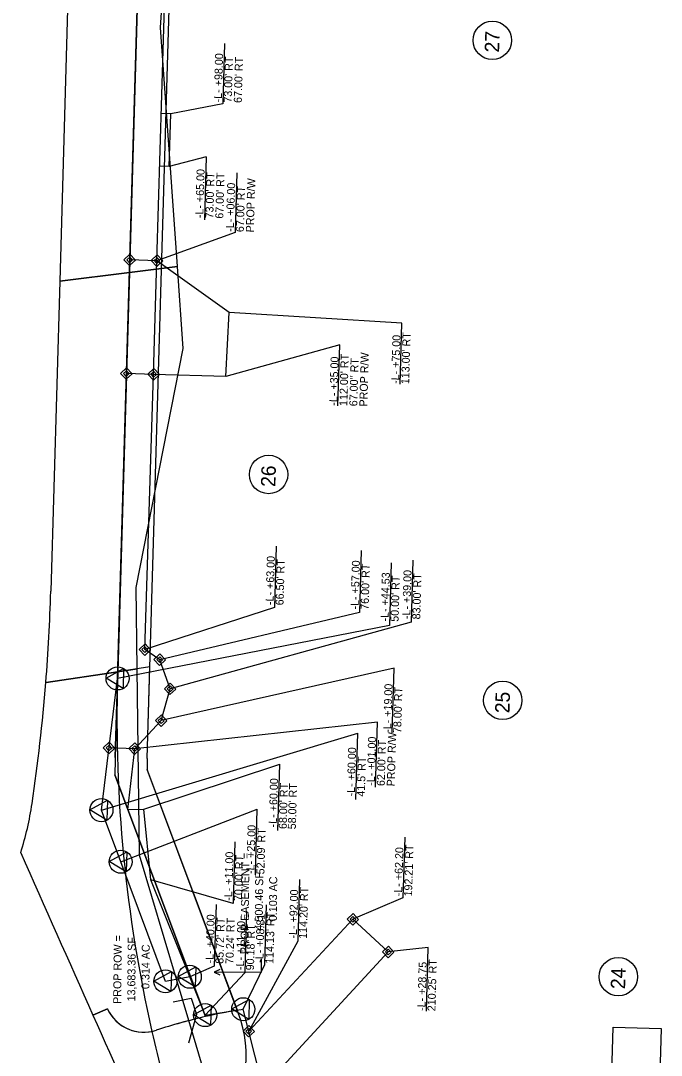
# Model space of a CAD drawing. Extents: x 2097272 to 2098144, y 685104 to 689282.
# Drawn here: x 2097691 to 2098091, y 685927 to 686573 of the extents above; entities that cross this region are included whole.
import ezdxf

# ---------------------------------------------------------------- set-up
doc = ezdxf.new("R2010")
doc.units = 0
for name, color, linetype in [('Prop Easement Construction', 7, 'Continuous'), ('Prop Easement Construction Station Offsets', 7, 'Continuous'), ('Prop Easement Permanent Drainage Utility', 7, 'Continuous'), ('Prop Easement Permanent Drainage Utility Station Offsets', 7, 'Continuous'), ('Prop Easement Permanent Utility', 7, 'Continuous'), ('Prop Easement Permanent Utility Station Offsets', 7, 'Continuous'), ('Prop Easement Temporary Drainage', 7, 'Continuous'), ('Prop Easement Temporary Drainage Station Offsets', 7, 'Continuous'), ('Prop Parcel Number CELL', 7, 'Continuous'), ('Prop ROW Marker CELL', 7, 'Continuous'), ('Prop ROW Permanent Easement CELL', 7, 'Continuous'), ('Prop ROW RW Lines', 7, 'Continuous'), ('Prop ROW Station Offsets', 7, 'Continuous'), ('Scratch_Level_3', 7, 'Continuous'), ('Scratch_Level_5', 7, 'Continuous'), ('Scratch_Level_6', 7, 'Continuous'), ('Scratch_Level_7', 7, 'Continuous')]:
    doc.layers.add(name, color=color, linetype=linetype)

msp = doc.modelspace()

# ---------------------------------------------------------------- linework, layer by layer
at = {"layer": 'Prop Easement Construction'}
for p, q in [((2097785.08, 686514.81), (2097779.09, 686514.98)), ((2097784.12, 686481.82), (2097785.08, 686514.81)), ((2097784.12, 686481.82), (2097778.13, 686482)), ((2097758.24, 686080.27), (2097762.55, 686118.29)), ((2097758.24, 686080.27), (2097768.23, 686080.47)), ((2097772.63, 686036.38), (2097768.23, 686080.47)), ((2097796.9, 685975.9), (2097772.63, 686036.38))]:
    msp.add_line(p, q, dxfattribs=at)
at = {"layer": 'Prop Easement Construction Station Offsets'}
for p, q in [((2097818.67, 686558.72), (2097817.57, 686520.89)), ((2097817.57, 686520.89), (2097785.08, 686514.81)), ((2097807.18, 686487.95), (2097784.12, 686481.82)), ((2097807.18, 686487.95), (2097806.04, 686448.6)), ((2097768.23, 686080.47), (2097853.06, 686108.63)), ((2097851.85, 686067.2), (2097853.06, 686108.63)), ((2097825.03, 686060.17), (2097823.91, 686021.63)), ((2097823.91, 686021.63), (2097772.63, 686036.38))]:
    msp.add_line(p, q, dxfattribs=at)
at = {"layer": 'Prop Easement Permanent Drainage Utility'}
for p, q in [((2097776.41, 686423.02), (2097759.42, 686423.51)), ((2097774.35, 686352.05), (2097776.41, 686423.02)), ((2097774.35, 686352.05), (2097757.36, 686352.54))]:
    msp.add_line(p, q, dxfattribs=at)
at = {"layer": 'Prop Easement Permanent Drainage Utility Station Offsets'}
for p, q in [((2097826.22, 686477.88), (2097825.14, 686440.63)), ((2097825.14, 686440.63), (2097776.41, 686423.02))]:
    msp.add_line(p, q, dxfattribs=at)
at = {"layer": 'Prop Easement Permanent Utility'}
for p, q in [((2097768.85, 686180.14), (2097774.35, 686352.05)), ((2097778.17, 686173.86), (2097768.85, 686180.14)), ((2097784.65, 686155.67), (2097778.17, 686173.86)), ((2097779.07, 686135.82), (2097784.65, 686155.67)), ((2097762.55, 686118.29), (2097779.07, 686135.82)), ((2097762.55, 686118.29), (2097746.5, 686118.76)), ((2097898.73, 686011.78), (2097833.74, 685941.88)), ((2097920.79, 685991.37), (2097898.73, 686011.78)), ((2097842.65, 685906.79), (2097920.79, 685991.37))]:
    msp.add_line(p, q, dxfattribs=at)
msp.add_lwpolyline([(2097776.41, 686423.02), (2097781.44, 686595.95)], dxfattribs=at)
at = {"layer": 'Prop Easement Permanent Utility Station Offsets'}
for p, q in [((2097850.86, 686244.85), (2097849.74, 686206.41)), ((2097903.93, 686242.07), (2097902.81, 686203.4)), ((2097936.21, 686236.07), (2097935.08, 686197.36)), ((2097849.74, 686206.41), (2097768.85, 686180.14)), ((2097902.81, 686203.4), (2097778.17, 686173.86)), ((2097935.08, 686197.36), (2097784.65, 686155.67)), ((2097924.46, 686168.68), (2097779.07, 686135.82)), ((2097923.28, 686128.13), (2097924.46, 686168.68)), ((2097914.02, 686134.92), (2097762.55, 686118.29)), ((2097912.84, 686094.37), (2097914.02, 686134.92)), ((2097931.1, 686063.03), (2097929.99, 686025.16)), ((2097865.41, 686036.58), (2097864.29, 685998.04)), ((2097929.99, 686025.16), (2097898.73, 686011.78)), ((2097864.29, 685998.04), (2097833.74, 685941.88)), ((2097945.75, 685994.23), (2097920.79, 685991.37)), ((2097944.6, 685954.48), (2097945.75, 685994.23))]:
    msp.add_line(p, q, dxfattribs=at)
at = {"layer": 'Prop Easement Temporary Drainage'}
for p, q in [((2097821.49, 686390.7), (2097776.41, 686423.02)), ((2097819.33, 686350.74), (2097821.49, 686390.7)), ((2097819.33, 686350.74), (2097774.35, 686352.05))]:
    msp.add_line(p, q, dxfattribs=at)
at = {"layer": 'Prop Easement Temporary Drainage Station Offsets'}
for p, q in [((2097929.31, 686384.08), (2097821.49, 686390.7)), ((2097928.2, 686345.99), (2097929.31, 686384.08)), ((2097890.54, 686370.56), (2097819.33, 686350.74)), ((2097889.43, 686332.4), (2097890.54, 686370.56))]:
    msp.add_line(p, q, dxfattribs=at)
at = {"layer": 'Prop Parcel Number CELL'}
msp.add_lwpolyline([(2098058.38, 685844.55), (2098061.29, 685944.51), (2098091.27, 685943.64), (2098088.37, 685843.68)], close=True, dxfattribs=at)
for centre in [(2097985.79, 686560.59), (2097846.11, 686289.52), (2097992.27, 686148.48), (2098064.45, 685975.93)]:
    msp.add_circle(centre, 12, dxfattribs=at)
at = {"layer": 'Prop ROW Marker CELL'}
for p, q in [((2097759.42, 686423.51), (2097759.42, 686423.51)), ((2097776.41, 686423.02), (2097776.41, 686423.02)), ((2097757.36, 686352.54), (2097757.36, 686352.54)), ((2097774.35, 686352.05), (2097774.35, 686352.05)), ((2097751.82, 686162.16), (2097751.82, 686162.16)), ((2097784.65, 686155.67), (2097784.65, 686155.67)), ((2097779.07, 686135.82), (2097779.07, 686135.82)), ((2097746.5, 686118.76), (2097746.5, 686118.76)), ((2097762.55, 686118.29), (2097762.55, 686118.29)), ((2097741.74, 686079.93), (2097741.74, 686079.93)), ((2097753.77, 686047.73), (2097753.77, 686047.73)), ((2097898.73, 686011.78), (2097898.73, 686011.78)), ((2097920.79, 685991.37), (2097920.79, 685991.37)), ((2097781.69, 685973.01), (2097781.69, 685973.01)), ((2097796.9, 685975.9), (2097796.9, 685975.9)), ((2097830.26, 685955.58), (2097830.26, 685955.58)), ((2097806.52, 685951.94), (2097806.52, 685951.94)), ((2097833.74, 685941.88), (2097833.74, 685941.88))]:
    msp.add_line(p, q, dxfattribs=at)
for points in [[(2097755.24, 686155.8), (2097744.62, 686162.36), (2097755.6, 686168.3)], [(2097745.16, 686073.58), (2097734.54, 686080.14), (2097745.52, 686086.08)], [(2097757.19, 686041.38), (2097746.57, 686047.94), (2097757.55, 686053.88)], [(2097785.1, 685966.66), (2097774.49, 685973.22), (2097785.47, 685979.15)], [(2097800.32, 685969.55), (2097789.71, 685976.11), (2097800.68, 685982.05)], [(2097833.68, 685949.22), (2097823.06, 685955.79), (2097834.04, 685961.72)], [(2097809.93, 685945.59), (2097799.32, 685952.15), (2097810.3, 685958.08)]]:
    msp.add_lwpolyline(points, close=True, dxfattribs=at)
for centre in [(2097751.82, 686162.16), (2097741.74, 686079.93), (2097753.77, 686047.73), (2097781.69, 685973.01), (2097796.9, 685975.9), (2097806.52, 685951.94), (2097830.26, 685955.58)]:
    msp.add_circle(centre, 7.2, dxfattribs=at)
at = {"layer": 'Prop ROW Permanent Easement CELL'}
for p, q in [((2097768.85, 686180.14), (2097768.85, 686180.14)), ((2097778.17, 686173.86), (2097778.17, 686173.86))]:
    msp.add_line(p, q, dxfattribs=at)
for points in [[(2097755.82, 686423.62), (2097759.52, 686427.11), (2097763.02, 686423.41), (2097759.32, 686419.92)], [(2097757.62, 686423.57), (2097759.47, 686425.31), (2097761.22, 686423.46), (2097759.37, 686421.72)], [(2097772.81, 686423.12), (2097776.52, 686426.62), (2097780.01, 686422.92), (2097776.31, 686419.42)], [(2097774.61, 686423.07), (2097776.46, 686424.82), (2097778.21, 686422.97), (2097776.36, 686421.22)], [(2097753.76, 686352.65), (2097757.46, 686356.14), (2097760.95, 686352.44), (2097757.25, 686348.95)], [(2097755.56, 686352.6), (2097757.41, 686354.34), (2097759.16, 686352.49), (2097757.3, 686350.75)], [(2097770.75, 686352.15), (2097774.45, 686355.65), (2097777.95, 686351.95), (2097774.25, 686348.45)], [(2097772.55, 686352.1), (2097774.4, 686353.85), (2097776.15, 686352), (2097774.3, 686350.25)], [(2097765.25, 686180.24), (2097768.96, 686183.74), (2097772.45, 686180.03), (2097768.75, 686176.54)], [(2097767.05, 686180.19), (2097768.9, 686181.94), (2097770.65, 686180.09), (2097768.8, 686178.34)], [(2097774.57, 686173.97), (2097778.28, 686177.46), (2097781.77, 686173.76), (2097778.07, 686170.27)], [(2097776.37, 686173.92), (2097778.23, 686175.66), (2097779.97, 686173.81), (2097778.12, 686172.07)], [(2097781.05, 686155.77), (2097784.75, 686159.27), (2097788.24, 686155.56), (2097784.54, 686152.07)], [(2097782.85, 686155.72), (2097784.7, 686157.47), (2097786.45, 686155.62), (2097784.59, 686153.87)], [(2097775.47, 686135.93), (2097779.17, 686139.42), (2097782.67, 686135.72), (2097778.96, 686132.22)], [(2097777.27, 686135.87), (2097779.12, 686137.62), (2097780.87, 686135.77), (2097779.02, 686134.02)], [(2097742.9, 686118.87), (2097746.61, 686122.36), (2097750.1, 686118.66), (2097746.4, 686115.16)], [(2097744.7, 686118.81), (2097746.55, 686120.56), (2097748.3, 686118.71), (2097746.45, 686116.96)], [(2097758.95, 686118.4), (2097762.66, 686121.89), (2097766.15, 686118.19), (2097762.45, 686114.7)], [(2097760.75, 686118.35), (2097762.6, 686120.09), (2097764.35, 686118.24), (2097762.5, 686116.5)], [(2097895.14, 686011.89), (2097898.84, 686015.38), (2097902.33, 686011.68), (2097898.63, 686008.18)], [(2097896.94, 686011.83), (2097898.79, 686013.58), (2097900.53, 686011.73), (2097898.68, 686009.98)], [(2097917.19, 685991.48), (2097920.89, 685994.97), (2097924.38, 685991.27), (2097920.68, 685987.77)], [(2097918.99, 685991.42), (2097920.84, 685993.17), (2097922.59, 685991.32), (2097920.74, 685989.57)], [(2097830.14, 685941.99), (2097833.84, 685945.48), (2097837.34, 685941.78), (2097833.63, 685938.28)], [(2097831.94, 685941.93), (2097833.79, 685943.68), (2097835.54, 685941.83), (2097833.69, 685940.08)]]:
    msp.add_lwpolyline(points, close=True, dxfattribs=at)
at = {"layer": 'Prop ROW RW Lines'}
for p, q in [((2097751.82, 686162.16), (2097773.16, 686896.33)), ((2097741.74, 686079.93), (2097751.82, 686162.16)), ((2097753.77, 686047.73), (2097741.74, 686079.93)), ((2097781.69, 685973.01), (2097753.77, 686047.73)), ((2097796.9, 685975.9), (2097781.69, 685973.01)), ((2097806.52, 685951.94), (2097796.9, 685975.9)), ((2097806.52, 685951.94), (2097830.26, 685955.58)), ((2097842.65, 685906.79), (2097830.26, 685955.58))]:
    msp.add_line(p, q, dxfattribs=at)
at = {"layer": 'Prop ROW Station Offsets'}
for p, q in [((2097922.65, 686234.37), (2097921.51, 686195.26)), ((2097921.51, 686195.26), (2097751.82, 686162.16)), ((2097741.74, 686079.93), (2097901.8, 686127.96)), ((2097900.6, 686086.53), (2097901.8, 686127.96)), ((2097753.77, 686047.73), (2097839.04, 686080.57)), ((2097837.85, 686039.54), (2097839.04, 686080.57)), ((2097813.35, 686021.05), (2097812.23, 685982.52)), ((2097832.38, 686016.92), (2097831.26, 685978.39)), ((2097843.68, 685983.62), (2097844.77, 686020.82)), ((2097812.23, 685982.52), (2097796.9, 685975.9)), ((2097831.26, 685978.39), (2097806.52, 685951.94)), ((2097830.26, 685955.58), (2097843.68, 685983.62))]:
    msp.add_line(p, q, dxfattribs=at)
at = {"layer": 'Scratch_Level_3'}
for p, q in [((2097722.93, 686658.13), (2097715.74, 686410.2)), ((2097759.19, 686415.67), (2097766.15, 686654.89)), ((2097759.19, 686415.67), (2097715.74, 686410.2)), ((2097715.74, 686410.2), (2097759.19, 686415.67)), ((2097751.94, 686166.34), (2097759.19, 686415.67)), ((2097715.74, 686410.2), (2097710.12, 686216.57)), ((2097751.94, 686166.34), (2097707.35, 686159.6)), ((2097707.35, 686159.6), (2097751.94, 686166.34)), ((2097751.82, 686162.17), (2097751.94, 686166.34)), ((2097707.35, 686159.6), (2097707.03, 686159.55)), ((2097707.03, 686159.55), (2097707.35, 686159.6)), ((2097745.48, 685955.96), (2097736.46, 685951.87)), ((2097736.46, 685951.87), (2097745.48, 685955.96))]:
    msp.add_line(p, q, dxfattribs=at)
for centre, radius, start, end in [((2096580.6, 686249.32), 1130, 355.44359, 358.33912), ((2096580.6, 686249.32), 1130, 351.59142, 355.44359), ((2098631.45, 686136.6), 880, 178.33483, 192.79074), ((2097503.07, 686112.96), 197.5, 342.42468, 351.59142), ((2162207.31, 714677.79), 70580.94, 203.9259247, 204.016055), ((2097768.26, 685966.27), 25, 204.34976, 281.6101), ((2097768.26, 685966.27), 25, 204.34976, 281.6101), ((2162207.31, 714677.79), 70580.94, 204.016055, 204.097808), ((2098631.45, 686136.6), 880, 192.79074, 196.50581)]:
    msp.add_arc(centre, radius, start, end, dxfattribs=at)
at = {"layer": 'Scratch_Level_5'}
for p, q in [((2097770.38, 686112.18), (2097793.16, 686895.75)), ((2097751.94, 686166.34), (2097707.35, 686159.6)), ((2097750.39, 686112.76), (2097751.94, 686166.34)), ((2097751.94, 686166.34), (2097750.39, 686112.76)), ((2097772.04, 686169.38), (2097751.94, 686166.34)), ((2097770.38, 686112.18), (2097772.04, 686169.38)), ((2097707.35, 686159.6), (2097707.03, 686159.55)), ((2097806.72, 685951.02), (2097750.16, 686101.88)), ((2097750.16, 686101.88), (2097806.72, 685951.02)), ((2097827.21, 685953.34), (2097770.21, 686105.36)), ((2097826.6, 685954.98), (2097770.21, 686105.36)), ((2097841.56, 685987), (2097841.48, 685978.46)), ((2097815.69, 685980.36), (2097812.1, 685978.73)), ((2097841.48, 685978.46), (2097812.1, 685978.73)), ((2097812.1, 685978.73), (2097815.65, 685977.03)), ((2097736.46, 685951.87), (2097745.48, 685955.96))]:
    msp.add_line(p, q, dxfattribs=at)
for centre, radius, start, end in [((2096580.6, 686249.32), 1130, 351.59142, 355.44359), ((2098415.1, 686093.44), 665, 178.33483, 179.2724), ((2098415.1, 686093.44), 665, 178.33483, 179.2724), ((2098415.1, 686093.44), 645, 178.33483, 178.94108), ((2098415.1, 686093.44), 645, 178.33483, 178.94108), ((2097503.07, 686112.96), 197.5, 342.42468, 351.59142), ((2162207.31, 714677.79), 70580.94, 203.9259247, 204.016055), ((2097768.26, 685966.27), 25, 204.34976, 288.11396), ((2097884.89, 685609.87), 350, 99.58713, 102.90531), ((2097754.89, 685926.19), 77.25, 323.48073, 20.60082), ((2097884.89, 685609.87), 350, 102.90531, 108.12134)]:
    msp.add_arc(centre, radius, start, end, dxfattribs=at)
at = {"layer": 'Scratch_Level_6'}
for p, q in [((2097766.15, 686654.89), (2097759.19, 686415.67)), ((2097778.65, 686568.71), (2097783.95, 686653.56)), ((2097789.2, 686419.45), (2097778.65, 686568.71)), ((2097759.19, 686415.67), (2097789.2, 686419.45)), ((2097789.2, 686419.45), (2097759.19, 686415.67)), ((2097792.83, 686368.21), (2097789.2, 686419.45)), ((2097759.19, 686415.67), (2097751.94, 686166.34)), ((2097763.48, 686219), (2097792.83, 686368.21)), ((2097764.12, 686168.18), (2097763.48, 686219)), ((2097751.94, 686166.34), (2097751.82, 686162.17)), ((2097751.94, 686166.34), (2097764.12, 686168.18)), ((2097764.12, 686168.18), (2097751.94, 686166.34)), ((2097765.6, 686051.77), (2097764.12, 686168.18)), ((2097796.42, 685948.5), (2097765.6, 686051.77)), ((2097810.75, 685900.48), (2097796.42, 685948.5))]:
    msp.add_line(p, q, dxfattribs=at)
for centre, radius, start, end in [((2098631.45, 686136.6), 880, 178.33483, 192.79074), ((2097884.89, 685609.87), 350, 104.64184, 108.12134), ((2097884.89, 685609.87), 350, 104.64184, 108.12134), ((2097768.26, 685966.27), 25, 281.6101, 288.11396), ((2097768.26, 685966.27), 25, 281.6101, 288.11396), ((2098631.45, 686136.6), 880, 192.79074, 196.50581)]:
    msp.add_arc(centre, radius, start, end, dxfattribs=at)
at = {"layer": 'Scratch_Level_7'}
for p, q in [((2097786.47, 685960.2), (2097797.82, 685962.6)), ((2097797.82, 685962.6), (2097801.11, 685952.34)), ((2097801.11, 685952.34), (2097796.12, 685934.38))]:
    msp.add_line(p, q, dxfattribs=at)

# ---------------------------------------------------------------- texts
at = {"layer": 'Prop Easement Construction Station Offsets'}
for s, p in [('-L- +98.00', (2097816.85, 686521.82)), ("73.00' RT", (2097823.09, 686521.64)), ("67.00' RT", (2097829.34, 686521.46)), ('-L- +65.00', (2097805.31, 686449.53)), ("73.00' RT", (2097811.56, 686449.35)), ("67.00' RT", (2097817.81, 686449.17)), ('-L- +60.00', (2097851.14, 686069.12)), ("68.00' RT", (2097857.39, 686068.07)), ("58.00' RT", (2097863.09, 686067.91)), ('-L- +11.00', (2097823.33, 686023.26)), ("70.00' RT", (2097829.58, 686023.08))]:
    msp.add_text(s, height=5, rotation=88.33483, dxfattribs=at).set_placement(p)
at = {"layer": 'Prop Easement Permanent Drainage Utility Station Offsets'}
for s, p in [('-L- +06.00', (2097824.39, 686440.98)), ("67.00' RT", (2097830.64, 686440.8)), ('PROP R/W', (2097836.89, 686440.62))]:
    msp.add_text(s, height=5, rotation=88.33483, dxfattribs=at).set_placement(p)
at = {"layer": 'Prop Easement Permanent Utility Station Offsets'}
for s, p in [('-L- +63.00', (2097849.16, 686207.94)), ("66.50' RT", (2097855.4, 686207.76)), ('-L- +57.00', (2097902.28, 686205.16)), ("76.00' RT", (2097908.53, 686204.98)), ('-L- +39.00', (2097934.51, 686199.17)), ("83.00' RT", (2097940.76, 686198.98)), ('-L- +19.00', (2097922.59, 686128.15)), ("78.00' RT", (2097928.84, 686127.97)), ('PROP R/W', (2097924.85, 686094.73)), ('-L- +01.00', (2097912.35, 686095.09)), ("62.00' RT", (2097918.6, 686094.91)), ('-L- +62.20', (2097929.4, 686026.12)), ("192.21' RT", (2097935.65, 686025.94)), ('-L- +92.00', (2097863.71, 685999.67)), ("114.20' RT", (2097869.96, 685999.49)), ('-L- +28.75', (2097943.97, 685954.5)), ("210.25' RT", (2097950.22, 685954.31))]:
    msp.add_text(s, height=5, rotation=88.33483, dxfattribs=at).set_placement(p)
at = {"layer": 'Prop Easement Temporary Drainage Station Offsets'}
for s, p in [('-L- +75.00', (2097927.58, 686346.01)), ("113.00' RT", (2097933.83, 686345.83)), ('PROP R/W', (2097907.71, 686331.87)), ('-L- +35.00', (2097888.97, 686332.42)), ("112.00' RT", (2097895.22, 686332.24)), ("67.00'' RT", (2097901.46, 686332.06))]:
    msp.add_text(s, height=5, rotation=88.33483, dxfattribs=at).set_placement(p)
at = {"layer": 'Prop Parcel Number CELL'}
for s, p in [('27', (2097989.99, 686552.92)), ('26', (2097850.3, 686281.65)), ('25', (2097996.46, 686140.35)), ('24', (2098068.65, 685968.05))]:
    msp.add_text(s, height=9, rotation=88.33483, dxfattribs=at).set_placement(p)
at = {"layer": 'Prop ROW Station Offsets'}
for s, p in [('-L- +44.53', (2097920.96, 686197.69)), ("50.00' RT", (2097927.2, 686197.51)), ('-L- +60.00', (2097899.89, 686088.45)), ("41.5' RT", (2097906.16, 686088.26)), ('-L- +25.00', (2097837.16, 686040.03)), ("52.09' RT", (2097843.44, 686039.78)), ('-L- +40.00', (2097811.65, 685984.14)), ("85.72' RT", (2097817.9, 685983.96)), ("70.24' RT", (2097824.15, 685983.78)), ('-L- +11.00', (2097830.68, 685980.01)), ('-L- +08.81', (2097842.82, 685984.56)), ("114.13' RT", (2097849.08, 685983.86)), ("90.18' RT", (2097836.93, 685979.83))]:
    msp.add_text(s, height=5, rotation=88.33483, dxfattribs=at).set_placement(p)
at = {"layer": 'Scratch_Level_5'}
for s, p in [('PROP EASEMENT =', (2097833.56, 685989.99)), ('4,500.46 SF', (2097842.45, 686004.77)), ('0.103 AC', (2097851.26, 686010.6)), ('PROP ROW =', (2097754.09, 685958.91)), ('13,683.36 SF', (2097762.85, 685960.47)), ('0.314 AC', (2097771.67, 685968.22))]:
    msp.add_text(s, height=5, rotation=89.46994, dxfattribs=at).set_placement(p)

doc.saveas('drawing.dxf')
